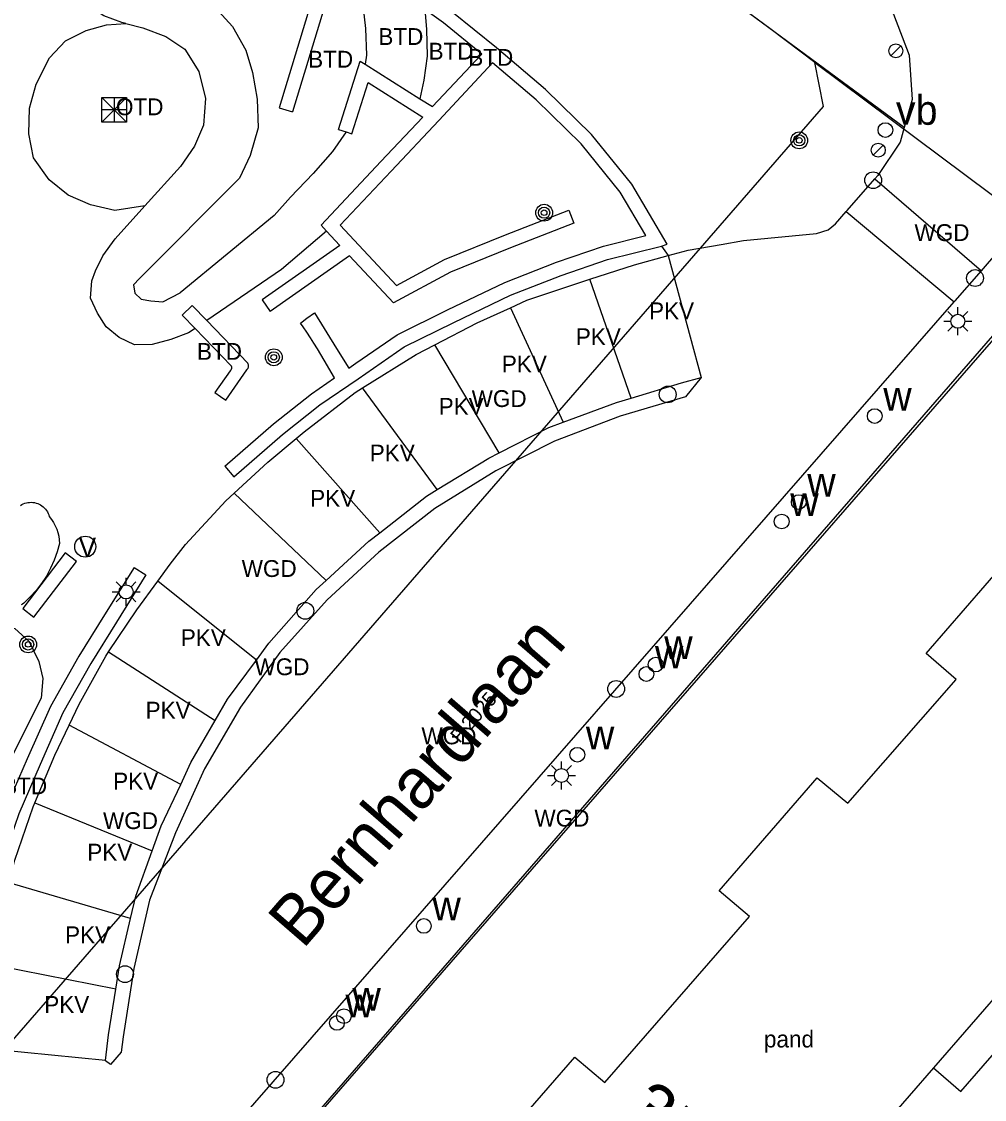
# Model space of a CAD drawing. Extents: x 198240 to 198429, y 356553 to 356721.
# Drawn here: x 198343.9 to 198378.24, y 356600.62 to 356639.08 of the extents above; entities that cross this region are included whole.
import ezdxf

# ---------------------------------------------------------------- set-up
doc = ezdxf.new("R2010")
doc.units = 0
for name, color, linetype in [('Afsluitpaal', 7, 'Continuous'), ('Afvalbak', 7, 'Continuous'), ('Bank', 7, 'Continuous'), ('begroeid terreindeel kenmerkpunt', 7, 'Continuous'), ('BOOM', 7, 'Continuous'), ('cultuurscheiding geen IMGeo', 7, 'Continuous'), ('grens individueel parkeervak', 7, 'Continuous'), ('Grens maaiveld', 7, 'Continuous'), ('grens WOZ object', 7, 'Continuous'), ('heg geen IMGeo', 7, 'Continuous'), ('hoofdgebouw', 7, 'Continuous'), ('huisnummerreeks BGT', 7, 'Continuous'), ('identificerend kenmerkpunt pand', 7, 'Continuous'), ('identificerend kenmerkpunt parkeervak', 7, 'Continuous'), ('kant verharding', 7, 'Continuous'), ('kolk', 7, 'Continuous'), ('LICHTMAST', 7, 'Continuous'), ('onbegroeid terreindeel kenmerkpunt', 7, 'Continuous'), ('openbare ruimte label tekst', 7, 'Continuous'), ('Perceelnummer', 7, 'Continuous'), ('perceelsgrens_definitief', 7, 'Continuous'), ('Speelvoorziening', 7, 'Continuous'), ('Verkeersbordpaal', 7, 'Continuous'), ('vlakafsluiter', 7, 'Continuous'), ('waterleidingput', 7, 'Continuous'), ('wegdeel kenmerkpunt', 7, 'Continuous'), ('weginrichtingselement lijn', 7, 'Continuous')]:
    doc.layers.add(name, color=color, linetype=linetype)

msp = doc.modelspace()

# ---------------------------------------------------------------- linework, layer by layer
at = {"layer": 'Afsluitpaal'}
for p, q in [((198375.256, 356638.211), (198374.906, 356637.854)), ((198374.628, 356634.667), (198374.278, 356634.31))]:
    msp.add_line(p, q, dxfattribs=at)
for centre in [(198375.083, 356638.031), (198374.455, 356634.487)]:
    msp.add_circle(centre, 0.25, dxfattribs=at)
at = {"layer": 'Afvalbak'}
msp.add_circle((198346.171, 356620.34), 0.375, dxfattribs=at)
msp.add_circle((198346.171, 356620.34), 0.375, dxfattribs=at)
at = {"layer": 'Bank'}
msp.add_lwpolyline([(198344.338, 356617.828), (198345.855, 356619.815), (198345.458, 356620.118), (198343.941, 356618.131)], close=True, dxfattribs=at)
at = {"layer": 'BOOM'}
for centre, radius in [((198371.637, 356634.836), 0.3), ((198371.637, 356634.836), 0.2), ((198371.637, 356634.836), 0.1), ((198362.537, 356632.255), 0.3), ((198362.537, 356632.255), 0.2), ((198362.537, 356632.255), 0.1), ((198352.895, 356627.097), 0.3), ((198352.895, 356627.097), 0.2), ((198352.895, 356627.097), 0.1), ((198344.134, 356616.852), 0.3), ((198344.134, 356616.852), 0.2), ((198344.134, 356616.852), 0.1)]:
    msp.add_circle(centre, radius, dxfattribs=at)
at = {"layer": 'cultuurscheiding geen IMGeo'}
msp.add_lwpolyline([(198348.3, 356632.503), (198347.23, 356632.333), (198346.355, 356632.531), (198345.562, 356632.883), (198344.882, 356633.43), (198344.323, 356634.217), (198344.155, 356635.075), (198344.181, 356635.987), (198344.418, 356636.839), (198344.894, 356637.777), (198345.466, 356638.388), (198346.203, 356638.76), (198346.924, 356638.961), (198347.617, 356639.006)], dxfattribs=at)
at = {"layer": 'grens individueel parkeervak'}
for p, q in [((198365.644, 356625.642), (198364.165, 356629.887)), ((198361.341, 356628.866), (198363.221, 356624.782)), ((198360.936, 356623.69), (198358.637, 356627.544)), ((198358.728, 356622.378), (198356.063, 356626.004)), ((198353.691, 356624.198), (198356.673, 356620.835)), ((198354.766, 356619.133), (198351.488, 356622.252)), ((198352.276, 356616.294), (198348.756, 356619.104)), ((198347.003, 356616.583), (198350.809, 356614.14)), ((198349.574, 356611.858), (198345.603, 356613.974)), ((198344.371, 356611.203), (198348.558, 356609.491)), ((198347.785, 356607.073), (198343.457, 356608.344)), ((198347.261, 356604.556), (198342.832, 356605.425))]:
    msp.add_line(p, q, dxfattribs=at)
at = {"layer": 'Grens maaiveld'}
for p, q in [((198355.201, 356635.227), (198355.979, 356637.664)), ((198355.979, 356637.664), (198356.155, 356637.553)), ((198360.315, 356637.918), (198358.555, 356636.041)), ((198356.155, 356637.553), (198358.109, 356636.322)), ((198360.7, 356637.598), (198358.778, 356635.549)), ((198355.677, 356635.075), (198356.259, 356636.896)), ((198356.259, 356636.896), (198358.206, 356635.67)), ((198358.109, 356636.322), (198358.555, 356636.041)), ((198353.086, 356636), (198353.564, 356635.854)), ((198358.206, 356635.67), (198356.713, 356634.079)), ((198358.778, 356635.549), (198357.077, 356633.737)), ((198355.201, 356635.227), (198355.475, 356635.14)), ((198355.475, 356635.14), (198355.677, 356635.075)), ((198357.077, 356633.737), (198355.267, 356631.807)), ((198374.327, 356633.463), (198378.133, 356630.181)), ((198361.154, 356631.468), (198363.421, 356632.343)), ((198363.421, 356632.343), (198363.601, 356631.877)), ((198354.781, 356631.594), (198355.256, 356631.085)), ((198355.267, 356631.807), (198357.269, 356629.662)), ((198363.601, 356631.877), (198361.338, 356631.004)), ((198358.981, 356630.588), (198361.154, 356631.468)), ((198366.718, 356631.056), (198366.931, 356631.131)), ((198355.256, 356631.085), (198352.477, 356629.141)), ((198361.338, 356631.004), (198359.195, 356630.136)), ((198355.6, 356630.716), (198352.763, 356628.731)), ((198357.167, 356629.038), (198355.6, 356630.716)), ((198357.269, 356629.662), (198358.981, 356630.588)), ((198359.195, 356630.136), (198357.167, 356629.038)), ((198352.477, 356629.141), (198352.763, 356628.731)), ((198353.852, 356628.315), (198354.071, 356628.491)), ((198354.071, 356628.491), (198354.343, 356628.683)), ((198354.343, 356628.683), (198355.132, 356627.414)), ((198353.939, 356628.188), (198353.852, 356628.315)), ((198354.07, 356627.992), (198353.939, 356628.188)), ((198354.2, 356627.795), (198354.07, 356627.992)), ((198354.326, 356627.597), (198354.2, 356627.795)), ((198354.451, 356627.397), (198354.326, 356627.597)), ((198354.574, 356627.195), (198354.451, 356627.397)), ((198355.132, 356627.414), (198355.569, 356626.711)), ((198354.694, 356626.992), (198354.574, 356627.195)), ((198355.062, 356626.363), (198354.694, 356626.992)), ((198355.569, 356626.711), (198355.818, 356626.883)), ((198354.24, 356625.798), (198355.062, 356626.363)), ((198352.884, 356624.725), (198354.24, 356625.798)), ((198351.145, 356623.211), (198352.884, 356624.725)), ((198351.145, 356623.211), (198351.473, 356622.833)), ((198347.91, 356619.599), (198348.334, 356619.335))]:
    msp.add_line(p, q, dxfattribs=at)
for points in [[(198347.617, 356639.006), (198347.475, 356639.042), (198346.828, 356639.275), (198346.287, 356639.639), (198345.935, 356640.096), (198345.691, 356640.614), (198345.65, 356641.176), (198345.843, 356643.252), (198346.007, 356643.901), (198346.27, 356644.596), (198346.627, 356645.198), (198347.603, 356646.563), (198348.274, 356647.167), (198349.119, 356647.571)], [(198355.423, 356642.194), (198355.054, 356642.463), (198353.086, 356636)], [(198355.432, 356641.569), (198355.328, 356641.645), (198353.564, 356635.854)], [(198355.703, 356641.372), (198355.885, 356640.7), (198356.064, 356639.773), (198356.166, 356638.829), (198356.197, 356637.88), (198356.155, 356637.553)], [(198360.838, 356638.137), (198359.247, 356639.427), (198358.39, 356640.042)], [(198350.809, 356639.574), (198351.421, 356638.896), (198351.9, 356638.053), (198352.132, 356637.263), (198352.304, 356636.304), (198352.335, 356635.286), (198352.056, 356634.3), (198351.678, 356633.487), (198348.107, 356629.905), (198347.893, 356629.681), (198347.934, 356629.384), (198348.165, 356629.174), (198348.512, 356629.113), (198348.934, 356629.081), (198349.56, 356629.397)], [(198358.285, 356639.502), (198358.345, 356638.809), (198358.369, 356637.843), (198358.247, 356636.985), (198358.109, 356636.322)], [(198360.315, 356637.918), (198358.943, 356639.029), (198358.285, 356639.502)], [(198348.3, 356632.503), (198347.23, 356632.333), (198346.355, 356632.531), (198345.562, 356632.883), (198344.882, 356633.43), (198344.323, 356634.217), (198344.155, 356635.075), (198344.181, 356635.987), (198344.418, 356636.839), (198344.894, 356637.777), (198345.466, 356638.388), (198346.203, 356638.76), (198346.924, 356638.961), (198347.617, 356639.006)], [(198347.617, 356639.006), (198348.223, 356638.853), (198349.044, 356638.542), (198349.72, 356638.092), (198350.224, 356637.297), (198350.464, 356636.329), (198350.391, 356635.382), (198350.065, 356634.626), (198349.568, 356633.901), (198348.3, 356632.503)], [(198366.931, 356631.131), (198365.663, 356633.274), (198364.225, 356635.046), (198362.589, 356636.649), (198360.838, 356638.137)], [(198366.169, 356631.437), (198365.251, 356632.988), (198363.855, 356634.708), (198362.251, 356636.279), (198360.7, 356637.598)], [(198355.475, 356635.14), (198354.984, 356634.444), (198354.299, 356633.652), (198353.486, 356632.812), (198352.904, 356632.154), (198349.56, 356629.397)], [(198356.713, 356634.079), (198354.581, 356631.807), (198354.781, 356631.594)], [(198350.087, 356628.126), (198349.855, 356627.967), (198349.219, 356627.732), (198348.552, 356627.55), (198347.927, 356627.546), (198347.384, 356627.804), (198346.912, 356628.184), (198346.605, 356628.667), (198346.363, 356629.206), (198346.407, 356629.824), (198346.536, 356630.187), (198346.793, 356630.721), (198347.232, 356631.327), (198348.3, 356632.503)], [(198354.781, 356631.594), (198353.174, 356630.235), (198350.505, 356628.412)], [(198355.818, 356626.883), (198357.29, 356627.901), (198359.094, 356628.794), (198361.134, 356629.767), (198362.979, 356630.491), (198364.657, 356631.066), (198366.169, 356631.437)], [(198355.899, 356626.331), (198357.544, 356627.469), (198359.312, 356628.344), (198361.334, 356629.309), (198363.151, 356630.021), (198364.797, 356630.586), (198366.718, 356631.056)], [(198350.505, 356628.412), (198349.989, 356628.95), (198349.632, 356628.6), (198350.087, 356628.126)], [(198350.087, 356628.126), (198351.373, 356626.786), (198351.378, 356626.776), (198351.382, 356626.765), (198351.385, 356626.753), (198351.387, 356626.742), (198351.389, 356626.73), (198351.389, 356626.718), (198351.388, 356626.705), (198351.386, 356626.692), (198351.383, 356626.68), (198351.379, 356626.668), (198351.374, 356626.657), (198351.368, 356626.646), (198351.361, 356626.635), (198351.353, 356626.626), (198351.344, 356626.617), (198351.334, 356626.609), (198350.797, 356625.836), (198350.991, 356625.701), (198351.18, 356625.57), (198351.933, 356626.653), (198351.94, 356626.661), (198351.951, 356626.672), (198351.961, 356626.684), (198351.97, 356626.697), (198351.978, 356626.711), (198351.984, 356626.725), (198351.989, 356626.74), (198351.993, 356626.755), (198351.995, 356626.77), (198351.997, 356626.786), (198351.996, 356626.802), (198351.995, 356626.817), (198351.992, 356626.832), (198351.987, 356626.847), (198351.982, 356626.862), (198351.975, 356626.876), (198351.967, 356626.889), (198350.505, 356628.412)], [(198368.144, 356626.379), (198367.583, 356625.689), (198365.254, 356624.993), (198362.903, 356624.104), (198360.818, 356623.043), (198358.637, 356621.707), (198356.643, 356620.14), (198354.803, 356618.445), (198353.108, 356616.568), (198351.709, 356614.61), (198350.422, 356612.416), (198349.39, 356610.128), (198348.468, 356607.725), (198347.9, 356605.284), (198347.524, 356602.855), (198347.455, 356602.308), (198347.074, 356601.861), (198346.895, 356601.995), (198346.896, 356602.006)], [(198351.473, 356622.833), (198353.204, 356624.341), (198354.538, 356625.396), (198355.899, 356626.331)], [(198343.857, 356621.81), (198343.907, 356621.84), (198343.96, 356621.866), (198344.014, 356621.887), (198344.071, 356621.904), (198344.128, 356621.915), (198344.186, 356621.921), (198344.245, 356621.923), (198344.303, 356621.919), (198344.361, 356621.91), (198344.418, 356621.897), (198344.474, 356621.878), (198344.527, 356621.855), (198344.579, 356621.827), (198344.628, 356621.794), (198344.674, 356621.758), (198344.716, 356621.718), (198344.755, 356621.674), (198344.79, 356621.627), (198344.821, 356621.577), (198344.848, 356621.525), (198344.869, 356621.471), (198344.886, 356621.415), (198344.968, 356621.312), (198345.04, 356621.203), (198345.102, 356621.088), (198345.154, 356620.968), (198345.195, 356620.843), (198345.225, 356620.716), (198345.243, 356620.586), (198345.25, 356620.456), (198345.169, 356620.151), (198345.063, 356619.854), (198344.934, 356619.567), (198344.783, 356619.29), (198344.611, 356619.026), (198344.418, 356618.777), (198344.206, 356618.544), (198343.976, 356618.328), (198343.93, 356618.292), (198343.881, 356618.259)], [(198347.91, 356619.599), (198346.861, 356617.91), (198345.941, 356616.427), (198344.929, 356614.639), (198344.101, 356612.773), (198343.329, 356610.981), (198342.7, 356609.121), (198342.579, 356608.462)], [(198348.334, 356619.335), (198347.285, 356617.646), (198346.371, 356616.173), (198345.377, 356614.413), (198344.559, 356612.573), (198343.797, 356610.801), (198343.186, 356608.995), (198343.075, 356608.396)]]:
    msp.add_lwpolyline(points, dxfattribs=at)
at = {"layer": 'grens WOZ object'}
msp.add_lwpolyline([(198376.42, 356601.748), (198377.399, 356600.897), (198380.113, 356604.018), (198379.134, 356604.869)], dxfattribs=at)
at = {"layer": 'heg geen IMGeo'}
for points in [[(198360.838, 356638.137), (198359.247, 356639.427), (198358.39, 356640.042)], [(198360.315, 356637.918), (198358.943, 356639.029), (198358.285, 356639.502)], [(198366.931, 356631.131), (198365.663, 356633.274), (198364.225, 356635.046), (198362.589, 356636.649), (198360.838, 356638.137)], [(198366.169, 356631.437), (198365.251, 356632.988), (198363.855, 356634.708), (198362.251, 356636.279), (198360.7, 356637.598)]]:
    msp.add_lwpolyline(points, dxfattribs=at)
at = {"layer": 'hoofdgebouw'}
for p, q in [((198379.134, 356604.869), (198376.42, 356601.748)), ((198376.42, 356601.748), (198371.066, 356595.591))]:
    msp.add_line(p, q, dxfattribs=at)
msp.add_lwpolyline([(198360.274, 356583.182), (198357.56, 356580.061), (198351.153, 356585.634), (198353.818, 356588.702), (198352.758, 356589.611), (198356.269, 356593.637), (198357.324, 356592.737), (198361.192, 356597.186), (198360.148, 356598.119), (198363.635, 356602.123), (198364.703, 356601.223), (198369.86, 356607.147), (198368.781, 356608.057), (198372.281, 356612.093), (198373.369, 356611.185), (198377.239, 356615.604), (198376.168, 356616.531), (198379.668, 356620.576), (198380.75, 356619.653), (198383.405, 356622.721), (198387.106, 356619.502)], dxfattribs=at)
at = {"layer": 'kant verharding'}
for p, q in [((198373.346, 356632.34), (198374.327, 356633.463)), ((198373.315, 356632.304), (198373.346, 356632.34)), ((198366.966, 356630.723), (198368.144, 356626.379)), ((198377.2, 356629.113), (198378.133, 356630.181)), ((198344.897, 356592.108), (198377.168, 356629.077)), ((198377.168, 356629.077), (198377.2, 356629.113)), ((198346.896, 356602.006), (198342.457, 356602.444))]:
    msp.add_line(p, q, dxfattribs=at)
for points in [[(198375.379, 356635.292), (198365.453, 356642.617), (198363.834, 356643.796), (198358.657, 356647.515), (198356.63, 356648.904), (198355.686, 356649.56)], [(198373.454, 356641.134), (198374.046, 356640.603), (198374.994, 356639.335), (198375.554, 356637.877), (198375.659, 356636.295), (198375.379, 356635.292)], [(198375.379, 356635.292), (198375.236, 356634.777), (198374.436, 356633.588), (198374.327, 356633.463)], [(198368.856, 356631.126), (198369.651, 356631.268), (198372.254, 356631.517), (198372.669, 356631.642), (198372.933, 356631.857), (198373.315, 356632.304)], [(198378.133, 356630.181), (198378.722, 356630.856), (198379.929, 356631.864), (198381.394, 356632.501)], [(198366.966, 356630.723), (198367.678, 356630.916), (198368.856, 356631.126)], [(198382.054, 356630.413), (198380.73, 356630.231), (198344.191, 356588.273)], [(198364.165, 356629.887), (198365.761, 356630.397), (198366.966, 356630.723)], [(198361.341, 356628.866), (198361.926, 356629.132), (198364.165, 356629.887)], [(198358.637, 356627.544), (198360.154, 356628.327), (198361.341, 356628.866)], [(198356.063, 356626.004), (198357.978, 356627.198), (198358.637, 356627.544)], [(198365.644, 356625.642), (198367.437, 356626.189), (198368.144, 356626.379)], [(198353.691, 356624.198), (198353.981, 356624.441), (198355.796, 356625.838), (198356.063, 356626.004)], [(198363.221, 356624.782), (198365.115, 356625.481), (198365.644, 356625.642)], [(198360.936, 356623.69), (198362.707, 356624.593), (198363.221, 356624.782)], [(198351.488, 356622.252), (198352.682, 356623.349), (198353.691, 356624.198)], [(198358.728, 356622.378), (198360.564, 356623.501), (198360.936, 356623.69)], [(198356.673, 356620.835), (198358.345, 356622.143), (198358.728, 356622.378)], [(198348.756, 356619.104), (198349.202, 356619.716), (198349.751, 356620.419), (198351.187, 356621.975), (198351.488, 356622.252)], [(198354.766, 356619.133), (198356.287, 356620.533), (198356.673, 356620.835)], [(198347.003, 356616.583), (198348.015, 356618.087), (198348.756, 356619.104)], [(198352.276, 356616.294), (198352.721, 356616.899), (198354.411, 356618.807), (198354.766, 356619.133)], [(198340.669, 356616.839), (198341.075, 356617.188), (198341.657, 356617.431), (198342.242, 356617.588), (198343.015, 356617.587), (198343.659, 356617.423), (198344.172, 356616.956), (198344.514, 356616.245), (198344.663, 356615.631), (198344.6, 356614.936), (198342.14, 356610.048), (198341.84, 356609.575), (198341.293, 356609.087), (198340.786, 356608.703)], [(198345.603, 356613.974), (198345.958, 356614.719), (198346.904, 356616.435), (198347.003, 356616.583)], [(198350.809, 356614.14), (198351.246, 356614.894), (198352.276, 356616.294)], [(198344.371, 356611.203), (198345.09, 356612.899), (198345.603, 356613.974)], [(198349.574, 356611.858), (198349.939, 356612.638), (198350.809, 356614.14)], [(198348.558, 356609.491), (198348.88, 356610.376), (198349.574, 356611.858)], [(198343.457, 356608.344), (198343.66, 356609.157), (198344.31, 356611.059), (198344.371, 356611.203)], [(198347.785, 356607.073), (198347.97, 356607.872), (198348.558, 356609.491)], [(198347.261, 356604.556), (198347.395, 356605.385), (198347.785, 356607.073)], [(198346.896, 356602.006), (198346.997, 356602.924), (198347.261, 356604.556)]]:
    msp.add_lwpolyline(points, dxfattribs=at)
at = {"layer": 'kolk'}
for centre in [(198374.275, 356633.414), (198377.907, 356629.924), (198366.946, 356625.772), (198354.018, 356618.051), (198365.106, 356615.263), (198347.589, 356605.084), (198352.957, 356601.318)]:
    msp.add_circle(centre, 0.3, dxfattribs=at)
at = {"layer": 'LICHTMAST'}
for p, q in [((198377.293, 356628.631), (198377.293, 356628.881)), ((198377.116, 356628.558), (198376.939, 356628.735)), ((198377.47, 356628.558), (198377.647, 356628.735)), ((198376.793, 356628.381), (198377.043, 356628.381)), ((198376.939, 356628.027), (198377.116, 356628.204)), ((198377.293, 356627.881), (198377.293, 356628.131)), ((198377.647, 356628.027), (198377.47, 356628.204)), ((198377.543, 356628.381), (198377.793, 356628.381)), ((198347.626, 356618.976), (198347.626, 356619.226)), ((198347.449, 356618.903), (198347.272, 356619.08)), ((198347.803, 356618.903), (198347.98, 356619.08)), ((198347.126, 356618.726), (198347.376, 356618.726)), ((198347.272, 356618.372), (198347.449, 356618.549)), ((198347.626, 356618.226), (198347.626, 356618.476)), ((198347.98, 356618.372), (198347.803, 356618.549)), ((198347.876, 356618.726), (198348.126, 356618.726)), ((198363.154, 356612.425), (198363.154, 356612.675)), ((198362.977, 356612.352), (198362.8, 356612.529)), ((198363.331, 356612.352), (198363.508, 356612.529)), ((198362.654, 356612.175), (198362.904, 356612.175)), ((198362.8, 356611.821), (198362.977, 356611.998)), ((198363.154, 356611.675), (198363.154, 356611.925)), ((198363.508, 356611.821), (198363.331, 356611.998)), ((198363.404, 356612.175), (198363.654, 356612.175))]:
    msp.add_line(p, q, dxfattribs=at)
for centre in [(198377.293, 356628.381), (198347.626, 356618.726), (198363.154, 356612.175)]:
    msp.add_circle(centre, 0.25, dxfattribs=at)
at = {"layer": 'perceelsgrens_definitief'}
for points in [[(198370.586, 356638.823), (198366.164, 356642.103), (198361.698, 356645.323), (198357.189, 356648.483), (198352.638, 356651.581), (198348.046, 356654.619), (198343.413, 356657.594), (198338.741, 356660.506), (198334.03, 356663.356), (198329.281, 356666.142), (198324.495, 356668.863), (198319.673, 356671.52), (198314.815, 356674.112)], [(198372.192, 356637.612), (198370.586, 356638.823)], [(198372.192, 356637.612), (198382.048, 356630.256)], [(198372.498, 356636.045), (198372.192, 356637.612)], [(198335.086, 356594.965), (198336.909, 356595.05), (198372.498, 356636.045)], [(198344.27, 356586.164), (198344.308, 356588.473), (198380.117, 356629.684), (198382.048, 356630.256)]]:
    msp.add_lwpolyline(points, dxfattribs=at)
at = {"layer": 'Speelvoorziening'}
for p, q in [((198346.765, 356636.367), (198347.645, 356636.367)), ((198346.765, 356635.487), (198346.765, 356636.367)), ((198346.765, 356636.367), (198347.645, 356635.487)), ((198346.765, 356635.487), (198347.645, 356636.367)), ((198347.205, 356636.367), (198347.205, 356635.487)), ((198347.645, 356636.367), (198347.645, 356635.487)), ((198347.645, 356635.927), (198346.765, 356635.927)), ((198347.645, 356635.487), (198346.765, 356635.487))]:
    msp.add_line(p, q, dxfattribs=at)
at = {"layer": 'Verkeersbordpaal'}
msp.add_circle((198374.709, 356635.203), 0.263, dxfattribs=at)
at = {"layer": 'vlakafsluiter'}
for p, q in [((198373.315, 356632.304), (198377.168, 356629.077)), ((198366.718, 356631.056), (198366.966, 356630.723))]:
    msp.add_line(p, q, dxfattribs=at)
at = {"layer": 'waterleidingput'}
for centre in [(198374.33, 356624.998), (198374.33, 356624.998), (198371.619, 356621.931), (198371.619, 356621.931), (198371.011, 356621.238), (198371.011, 356621.238), (198366.517, 356616.131), (198366.517, 356616.131), (198366.185, 356615.795), (198366.185, 356615.795), (198363.723, 356612.916), (198363.723, 356612.916), (198358.248, 356606.808), (198358.248, 356606.808), (198355.395, 356603.588), (198355.395, 356603.588), (198355.148, 356603.346), (198355.148, 356603.346)]:
    msp.add_circle(centre, 0.263, dxfattribs=at)
at = {"layer": 'weginrichtingselement lijn'}
msp.add_lwpolyline([(198368.144, 356626.379), (198367.583, 356625.689), (198365.254, 356624.993), (198362.903, 356624.104), (198360.818, 356623.043), (198358.637, 356621.707), (198356.643, 356620.14), (198354.803, 356618.445), (198353.108, 356616.568), (198351.709, 356614.61), (198350.422, 356612.416), (198349.39, 356610.128), (198348.468, 356607.725), (198347.9, 356605.284), (198347.524, 356602.855), (198347.455, 356602.308), (198347.074, 356601.861), (198346.895, 356601.995), (198346.896, 356602.006)], dxfattribs=at)

# ---------------------------------------------------------------- texts
at = {"layer": 'Afvalbak'}
msp.add_text('V', height=0.686, dxfattribs=at).set_placement((198345.943, 356619.969))
msp.add_text('V', height=0.686, dxfattribs=at).set_placement((198345.943, 356619.969))
at = {"layer": 'begroeid terreindeel kenmerkpunt'}
for p in [(198356.625, 356638.242), (198358.416, 356637.719), (198359.832, 356637.498), (198354.121, 356637.432), (198350.156, 356627.007), (198343.208, 356611.503)]:
    msp.add_text('BTD', height=0.6, dxfattribs=at).set_placement(p)
at = {"layer": 'huisnummerreeks BGT'}
msp.add_text('35-57', height=1.8, rotation=319, dxfattribs=at).set_placement((198365.268, 356600.059))
at = {"layer": 'identificerend kenmerkpunt pand'}
msp.add_text('pand', height=0.6, dxfattribs=at).set_placement((198370.378, 356602.47))
at = {"layer": 'identificerend kenmerkpunt parkeervak'}
for p in [(198366.28, 356628.454), (198363.668, 356627.531), (198361.03, 356626.558), (198358.776, 356625.046), (198356.318, 356623.38), (198354.193, 356621.766), (198349.58, 356616.793), (198348.325, 356614.205), (198347.166, 356611.675), (198346.244, 356609.138), (198345.451, 356606.191), (198344.708, 356603.705)]:
    msp.add_text('PKV', height=0.6, dxfattribs=at).set_placement(p)
at = {"layer": 'onbegroeid terreindeel kenmerkpunt'}
msp.add_text('OTD', height=0.6, dxfattribs=at).set_placement((198347.266, 356635.734))
at = {"layer": 'openbare ruimte label tekst'}
msp.add_text('Bernhardlaan', height=1.8, rotation=49.1, dxfattribs=at).set_placement((198353.931, 356605.944))
at = {"layer": 'Perceelnummer'}
msp.add_text('F 2025', height=0.5, rotation=49, dxfattribs=at).set_placement((198359.522, 356613.306))
at = {"layer": 'Verkeersbordpaal'}
msp.add_text('vb', height=1.05, dxfattribs=at).set_placement((198375.085, 356635.393))
at = {"layer": 'waterleidingput'}
for p in [(198374.634, 356625.196), (198371.923, 356622.129), (198371.315, 356621.436), (198366.821, 356616.329), (198366.489, 356615.993), (198364.027, 356613.114), (198358.552, 356607.006), (198355.699, 356603.786), (198355.452, 356603.544)]:
    msp.add_text('w', height=1.05, dxfattribs=at).set_placement(p)
at = {"layer": 'wegdeel kenmerkpunt'}
for p in [(198375.748, 356631.245), (198359.953, 356625.323), (198351.751, 356619.259), (198352.207, 356615.754), (198358.162, 356613.288), (198346.804, 356610.263), (198362.192, 356610.353)]:
    msp.add_text('WGD', height=0.6, dxfattribs=at).set_placement(p)

doc.saveas('drawing.dxf')
